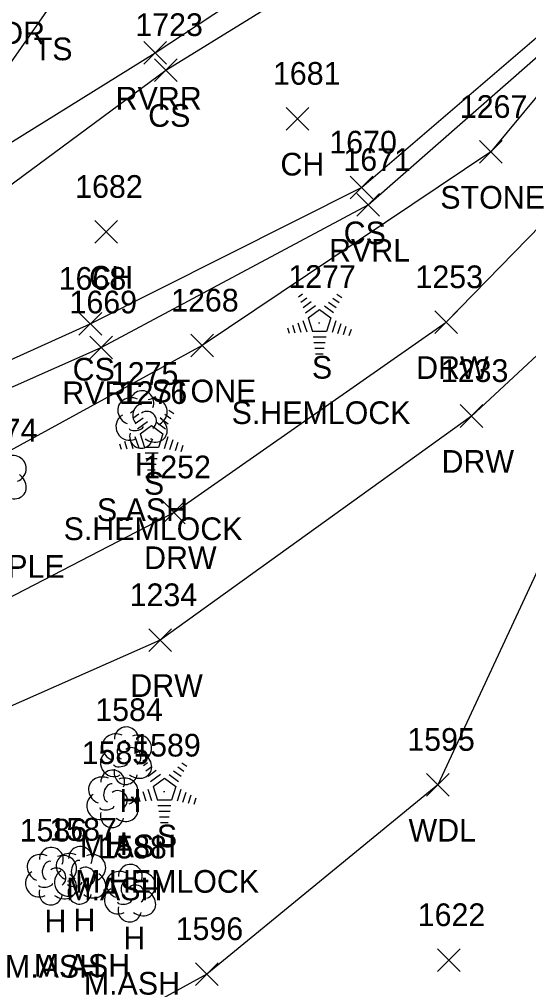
# Model space of a CAD drawing. Extents: x 1621633 to 1624015, y 417863 to 420979.
# Drawn here: x 1621938.6 to 1621983.5, y 417982.6 to 418067.9 of the extents above; entities that cross this region are included whole.
import ezdxf

# ---------------------------------------------------------------- set-up
doc = ezdxf.new("R2010")
doc.units = 0
for name, color, linetype in [('L_A', 7, 'Continuous'), ('L_C', 7, 'Continuous'), ('L_I', 7, 'Continuous'), ('L_TIC', 7, 'Continuous'), ('LASF', 7, 'Continuous'), ('LAWA', 7, 'Continuous'), ('LAWE', 7, 'Continuous'), ('LELB', 7, 'Continuous'), ('LTC', 7, 'Continuous'), ('LTD', 7, 'Continuous'), ('R_A', 7, 'Continuous'), ('R_I', 7, 'Continuous'), ('R_TIC', 7, 'Continuous'), ('RDW', 7, 'Continuous')]:
    doc.layers.add(name, color=color, linetype=linetype)

msp = doc.modelspace()

# ---------------------------------------------------------------- linework, layer by layer
at = {"layer": 'L_TIC'}
for points in [[(1621949.617, 418063.927), (1621951.617, 418065.927)], [(1621951.617, 418063.927), (1621949.617, 418065.927)], [(1621950.553, 418062.416), (1621952.553, 418064.416)], [(1621952.553, 418062.416), (1621950.553, 418064.416)], [(1621962.154, 418058.125), (1621964.154, 418060.125)], [(1621964.154, 418058.125), (1621962.154, 418060.125)], [(1621979.179, 418055.204), (1621981.179, 418057.204)], [(1621981.179, 418055.204), (1621979.179, 418057.204)], [(1621967.773, 418052.066), (1621969.773, 418054.066)], [(1621969.773, 418052.066), (1621967.773, 418054.066)], [(1621968.359, 418050.535), (1621970.359, 418052.535)], [(1621970.359, 418050.535), (1621968.359, 418052.535)], [(1621945.302, 418048.158), (1621947.302, 418050.158)], [(1621947.302, 418048.158), (1621945.302, 418050.158)], [(1621943.897, 418040.057), (1621945.897, 418042.057)], [(1621945.897, 418040.057), (1621943.897, 418042.057)], [(1621944.859, 418037.978), (1621946.859, 418039.978)], [(1621946.859, 418037.978), (1621944.859, 418039.978)], [(1621953.756, 418038.139), (1621955.756, 418040.139)], [(1621955.756, 418038.139), (1621953.756, 418040.139)], [(1621974.506, 417999.432), (1621976.506, 418001.432)], [(1621976.506, 417999.432), (1621974.506, 418001.432)], [(1621975.473, 417983.985), (1621977.473, 417985.985)], [(1621977.473, 417983.985), (1621975.473, 417985.985)], [(1621954.157, 417982.756), (1621956.157, 417984.756)], [(1621956.157, 417982.756), (1621954.157, 417984.756)]]:
    msp.add_lwpolyline(points, dxfattribs=at)
at = {"layer": 'LASF'}
msp.add_lwpolyline([(1622002.675, 418093.219), (1621997.296, 418076.86), (1621980.179, 418056.204), (1621954.756, 418039.139), (1621928.826, 418024.949), (1621900.016, 418015.523), (1621882.357, 418011.741)], dxfattribs=at)
at = {"layer": 'LAWA'}
msp.add_lwpolyline([(1622001.004, 418030.107), (1621986.32, 418023.658), (1621975.506, 418000.432), (1621955.157, 417983.756), (1621932.198, 417971.155), (1621904.748, 417967.466), (1621879.49, 417952.716), (1621860.189, 417941.587), (1621844.309, 417921.469), (1621821.118, 417913.626), (1621798.12, 417906.333), (1621768.531, 417901.526), (1621742.571, 417889.758), (1621727.863, 417881.174)], dxfattribs=at)
at = {"layer": 'LAWE'}
for points in [[(1621694.469, 417944.857), (1621713.846, 417956.733), (1621742.172, 417966.049), (1621760.532, 417975.456), (1621777.237, 417983.398), (1621792.696, 417991.301), (1621817.095, 418001.163), (1621844.467, 418008.037), (1621871.363, 418013.308), (1621897.422, 418019.495), (1621922.912, 418028.804), (1621945.859, 418038.978), (1621969.359, 418051.535), (1621990.012, 418069.674), (1621996.064, 418084.217), (1621996.533, 418092.287)], [(1621682.822, 417967.998), (1621698.064, 417979.126), (1621716.448, 417990.621), (1621740.687, 418004.296), (1621760.276, 418012.676), (1621779.786, 418018.1), (1621807.782, 418023.044), (1621832.841, 418028.899), (1621852.452, 418034.783), (1621876.37, 418040.125), (1621904.646, 418043.594), (1621931.259, 418052.925), (1621950.617, 418064.927), (1621964.804, 418074.349), (1621971.864, 418081.724)]]:
    msp.add_lwpolyline(points, dxfattribs=at)
at = {"layer": 'LELB'}
for points in [[(1621694.018, 417945.604), (1621713.058, 417958.392), (1621741.418, 417968.002), (1621759.92, 417977.729), (1621776.332, 417984.988), (1621792.046, 417992.579), (1621816.284, 418002.68), (1621844.088, 418009.589), (1621869.849, 418015.692), (1621896.837, 418021.913), (1621921.805, 418030.632), (1621944.897, 418041.057), (1621968.773, 418053.066), (1621989.111, 418070.538), (1621994.262, 418084.512), (1621994.522, 418092.07)], [(1621714.218, 417979.319), (1621742.211, 418002.577), (1621762.579, 418009.214), (1621780.28, 418013.608), (1621808.258, 418019.376), (1621833.473, 418026.83), (1621853.516, 418030.646), (1621878.098, 418035.973), (1621904.446, 418042.094), (1621933.372, 418049.997), (1621951.553, 418063.416), (1621967.003, 418072.955), (1621972.682, 418081.713), (1621977.304, 418089.793)], [(1621962.893, 418084.645), (1621941.499, 418069.284), (1621934.526, 418059.292), (1621911.153, 418049.766), (1621884.836, 418045.66), (1621868.891, 418041.418), (1621850.259, 418038.198), (1621830.712, 418031.899), (1621803.346, 418026.98), (1621784.312, 418024.309)]]:
    msp.add_lwpolyline(points, dxfattribs=at)
at = {"layer": 'LTC'}
for p, q in [((1621963.223, 418043.433), (1621963.578, 418043.691)), ((1621963.433, 418042.968), (1621963.962, 418043.352)), ((1621966.25, 418043.325), (1621966.8, 418042.926)), ((1621966.621, 418043.674), (1621967.041, 418043.369)), ((1621963.642, 418042.502), (1621964.346, 418043.013)), ((1621963.852, 418042.036), (1621964.73, 418042.674)), ((1621965.508, 418042.629), (1621966.318, 418042.04)), ((1621965.879, 418042.977), (1621966.558, 418042.483)), ((1621964.076, 418041.581), (1621965.088, 418042.316)), ((1621964.076, 418041.581), (1621964.463, 418040.388)), ((1621965.088, 418042.316), (1621966.085, 418041.591)), ((1621966.085, 418041.591), (1621965.694, 418040.388)), ((1621962.256, 418040.712), (1621962.408, 418040.244)), ((1621962.711, 418040.929), (1621962.923, 418040.277)), ((1621963.166, 418041.146), (1621963.438, 418040.31)), ((1621963.622, 418041.362), (1621963.953, 418040.343)), ((1621966.523, 418041.32), (1621966.185, 418040.28)), ((1621966.967, 418041.069), (1621966.68, 418040.185)), ((1621967.412, 418040.819), (1621967.175, 418040.09)), ((1621965.694, 418040.388), (1621964.463, 418040.388)), ((1621965.656, 418039.888), (1621964.511, 418039.888)), ((1621967.856, 418040.569), (1621967.669, 418039.995)), ((1621965.572, 418039.388), (1621964.583, 418039.388)), ((1621965.488, 418038.888), (1621964.656, 418038.888)), ((1621965.404, 418038.388), (1621964.729, 418038.388)), ((1621948.426, 418033.206), (1621948.78, 418033.463)), ((1621948.635, 418032.74), (1621949.164, 418033.124)), ((1621951.453, 418033.098), (1621952.002, 418032.699)), ((1621951.824, 418033.446), (1621952.243, 418033.142)), ((1621948.845, 418032.274), (1621949.549, 418032.786)), ((1621949.054, 418031.809), (1621949.933, 418032.447)), ((1621950.711, 418032.401), (1621951.52, 418031.812)), ((1621951.082, 418032.749), (1621951.761, 418032.256)), ((1621949.279, 418031.354), (1621950.291, 418032.088)), ((1621949.279, 418031.354), (1621949.666, 418030.16)), ((1621950.291, 418032.088), (1621951.288, 418031.363)), ((1621951.288, 418031.363), (1621950.897, 418030.16)), ((1621947.458, 418030.485), (1621947.61, 418030.017)), ((1621947.914, 418030.702), (1621948.125, 418030.05)), ((1621948.369, 418030.918), (1621948.64, 418030.083)), ((1621948.824, 418031.134), (1621949.155, 418030.115)), ((1621951.725, 418031.092), (1621951.387, 418030.053)), ((1621952.17, 418030.842), (1621951.882, 418029.957)), ((1621952.614, 418030.592), (1621952.377, 418029.862)), ((1621950.897, 418030.16), (1621949.666, 418030.16)), ((1621950.858, 418029.66), (1621949.714, 418029.66)), ((1621953.059, 418030.342), (1621952.872, 418029.767)), ((1621950.774, 418029.16), (1621949.786, 418029.16)), ((1621950.691, 418028.66), (1621949.859, 418028.66)), ((1621950.607, 418028.16), (1621949.932, 418028.16)), ((1621949.569, 418002.134), (1621949.924, 418002.391)), ((1621952.967, 418002.374), (1621953.387, 418002.069)), ((1621949.779, 418001.668), (1621950.308, 418002.052)), ((1621949.988, 418001.202), (1621950.692, 418001.714)), ((1621952.225, 418001.677), (1621952.905, 418001.184)), ((1621952.596, 418002.026), (1621953.146, 418001.626)), ((1621950.198, 418000.736), (1621951.076, 418001.374)), ((1621950.422, 418000.281), (1621951.434, 418001.016)), ((1621951.434, 418001.016), (1621952.431, 418000.291)), ((1621951.854, 418001.329), (1621952.664, 418000.74)), ((1621949.512, 417999.846), (1621949.784, 417999.011)), ((1621949.968, 418000.062), (1621950.299, 417999.043)), ((1621950.422, 418000.281), (1621950.81, 417999.088)), ((1621952.431, 418000.291), (1621952.04, 417999.088)), ((1621952.869, 418000.02), (1621952.531, 417998.981)), ((1621953.313, 417999.77), (1621953.026, 417998.885)), ((1621948.602, 417999.413), (1621948.754, 417998.945)), ((1621949.057, 417999.629), (1621949.269, 417998.978)), ((1621952.04, 417999.088), (1621950.81, 417999.088)), ((1621953.758, 417999.52), (1621953.521, 417998.79)), ((1621954.202, 417999.269), (1621954.015, 417998.695)), ((1621952.002, 417998.588), (1621950.857, 417998.588)), ((1621951.918, 417998.088), (1621950.93, 417998.088)), ((1621951.834, 417997.588), (1621951.002, 417997.588)), ((1621951.75, 417997.088), (1621951.075, 417997.088))]:
    msp.add_line(p, q, dxfattribs=at)
at = {"layer": 'LTD'}
for p, q in [((1621949.394, 418032.678), (1621949.394, 418032.678)), ((1621949.394, 418032.678), (1621949.394, 418032.678)), ((1621948.027, 418003.051), (1621948.027, 418003.051)), ((1621948.027, 418003.051), (1621948.027, 418003.051)), ((1621946.826, 417999.257), (1621946.826, 417999.257)), ((1621946.826, 417999.257), (1621946.826, 417999.257)), ((1621941.421, 417992.436), (1621941.421, 417992.436)), ((1621941.421, 417992.436), (1621941.421, 417992.436)), ((1621943.981, 417992.514), (1621943.981, 417992.514)), ((1621943.981, 417992.514), (1621943.981, 417992.514)), ((1621948.375, 417990.942), (1621948.375, 417990.942)), ((1621948.375, 417990.942), (1621948.375, 417990.942))]:
    msp.add_line(p, q, dxfattribs=at)
for centre in [(1621949.441, 418034.112), (1621948.074, 418004.485), (1621946.873, 418000.691), (1621941.468, 417993.87), (1621944.027, 417993.948), (1621948.421, 417992.376)]:
    msp.add_arc(centre, 1.047, 335.52715, 180.95627, dxfattribs=at)
for centre, major_axis, ratio, start_param, end_param in [((1621948.602, 418033.345), (1.21, -0.512), 0.895232, 1.570796, 4.712389), ((1621949.186, 418033.136), (-0.208, -0.792), 0.645439, 3.141593, 6.283185), ((1621950.436, 418033.262), (-1.141, -0.483), 0.949671, 1.570796, 4.712389), ((1621948.311, 418031.97), (0.584, -1.042), 0.959034, 3.141593, 6.283185), ((1621949.894, 418032.511), (-0.5, 0.667), 0.989748, 3.141593, 6.283185), ((1621950.394, 418031.845), (-1.09, 0.792), 0.841452, 1.570796, 4.712389), ((1621949.394, 418031.178), (0.265, 1.061), 0.942809, 1.570796, 4.712389), ((1621948.936, 418031.928), (-0.625, -0.083), 0.423636, 0, 3.141593), ((1621938.022, 418028.269), (-1.141, -0.483), 0.949671, 1.570796, 4.712389), ((1621937.98, 418026.852), (-1.09, 0.792), 0.841452, 1.570796, 4.712389), ((1621947.235, 418003.718), (1.21, -0.512), 0.895232, 1.570796, 4.712389), ((1621949.068, 418003.635), (-1.141, -0.483), 0.949671, 1.570796, 4.712389), ((1621947.818, 418003.51), (-0.208, -0.792), 0.645439, 3.141593, 6.283185), ((1621946.944, 418002.343), (0.584, -1.042), 0.959034, 3.141593, 6.283185), ((1621948.527, 418002.885), (-0.5, 0.667), 0.989748, 3.141593, 6.283185), ((1621949.027, 418002.218), (-1.09, 0.792), 0.841452, 1.570796, 4.712389), ((1621947.569, 418002.301), (-0.625, -0.083), 0.423636, 0, 3.141593), ((1621948.027, 418001.551), (0.265, 1.061), 0.942809, 1.570796, 4.712389), ((1621946.034, 417999.923), (1.21, -0.512), 0.895232, 1.570796, 4.712389), ((1621946.617, 417999.715), (-0.208, -0.792), 0.645439, 3.141593, 6.283185), ((1621947.867, 417999.84), (-1.141, -0.483), 0.949671, 1.570796, 4.712389), ((1621947.326, 417999.09), (-0.5, 0.667), 0.989748, 3.141593, 6.283185), ((1621945.743, 417998.548), (0.584, -1.042), 0.959034, 3.141593, 6.283185), ((1621947.826, 417998.424), (-1.09, 0.792), 0.841452, 1.570796, 4.712389), ((1621946.826, 417997.757), (0.265, 1.061), 0.942809, 1.570796, 4.712389), ((1621946.368, 417998.507), (-0.625, -0.083), 0.423636, 0, 3.141593), ((1621940.629, 417993.103), (1.21, -0.512), 0.895232, 1.570796, 4.712389), ((1621941.212, 417992.895), (-0.208, -0.792), 0.645439, 3.141593, 6.283185), ((1621943.189, 417993.18), (1.21, -0.512), 0.895232, 1.570796, 4.712389), ((1621942.462, 417993.02), (-1.141, -0.483), 0.949671, 1.570796, 4.712389), ((1621943.772, 417992.972), (-0.208, -0.792), 0.645439, 3.141593, 6.283185), ((1621945.022, 417993.097), (-1.141, -0.483), 0.949671, 1.570796, 4.712389), ((1621941.921, 417992.27), (-0.5, 0.667), 0.989748, 3.141593, 6.283185), ((1621944.481, 417992.347), (-0.5, 0.667), 0.989748, 3.141593, 6.283185), ((1621947.583, 417991.609), (1.21, -0.512), 0.895232, 1.570796, 4.712389), ((1621940.338, 417991.728), (0.584, -1.042), 0.959034, 3.141593, 6.283185), ((1621942.897, 417991.805), (0.584, -1.042), 0.959034, 3.141593, 6.283185), ((1621942.421, 417991.603), (-1.09, 0.792), 0.841452, 1.570796, 4.712389), ((1621944.981, 417991.68), (-1.09, 0.792), 0.841452, 1.570796, 4.712389), ((1621948.166, 417991.401), (-0.208, -0.792), 0.645439, 3.141593, 6.283185), ((1621949.416, 417991.526), (-1.141, -0.483), 0.949671, 1.570796, 4.712389), ((1621941.421, 417990.936), (0.265, 1.061), 0.942809, 1.570796, 4.712389), ((1621940.963, 417991.686), (-0.625, -0.083), 0.423636, 0, 3.141593), ((1621943.981, 417991.014), (0.265, 1.061), 0.942809, 1.570796, 4.712389), ((1621943.522, 417991.764), (-0.625, -0.083), 0.423636, 0, 3.141593), ((1621947.291, 417990.234), (0.584, -1.042), 0.959034, 3.141593, 6.283185), ((1621948.875, 417990.776), (-0.5, 0.667), 0.989748, 3.141593, 6.283185), ((1621949.375, 417990.109), (-1.09, 0.792), 0.841452, 1.570796, 4.712389), ((1621948.375, 417989.442), (0.265, 1.061), 0.942809, 1.570796, 4.712389), ((1621947.916, 417990.192), (-0.625, -0.083), 0.423636, 0, 3.141593)]:
    msp.add_ellipse(centre, major_axis=major_axis, ratio=ratio, start_param=start_param, end_param=end_param, dxfattribs=at)
at = {"layer": 'R_TIC'}
for points in [[(1621975.225, 418040.199), (1621977.225, 418042.199)], [(1621977.225, 418040.199), (1621975.225, 418042.199)], [(1621977.461, 418031.933), (1621979.461, 418033.933)], [(1621979.461, 418031.933), (1621977.461, 418033.933)], [(1621951.262, 418023.445), (1621953.262, 418025.445)], [(1621953.262, 418023.445), (1621951.262, 418025.445)], [(1621950.05, 418012.179), (1621952.05, 418014.179)], [(1621952.05, 418012.179), (1621950.05, 418014.179)]]:
    msp.add_lwpolyline(points, dxfattribs=at)
at = {"layer": 'RDW'}
for points in [[(1622068.286, 418109.151), (1622048.314, 418092.064), (1622031.513, 418075.622), (1622017.283, 418070.416), (1621999.079, 418052.056), (1621978.461, 418032.933), (1621951.05, 418013.179), (1621921.756, 418000.239), (1621894.363, 417990.232), (1621865.95, 417979.751)], [(1621869.66, 417990.005), (1621898.189, 417999.842), (1621925.17, 418010.412), (1621952.262, 418024.445), (1621976.225, 418041.199), (1621996.59, 418062.054), (1622014.164, 418083.988), (1622019.779, 418092.569), (1622014.506, 418097.249)]]:
    msp.add_lwpolyline(points, dxfattribs=at)

# ---------------------------------------------------------------- texts
at = {"layer": 'L_A'}
for s, p in [('WDR', (1621934.515, 418065.696)), ('TS', (1621939.909, 418064.284)), ('RVRR', (1621947.128, 418059.927)), ('CS', (1621949.994, 418058.416)), ('CH', (1621961.642, 418054.125)), ('STONE', (1621975.723, 418051.204)), ('CS', (1621967.214, 418048.066)), ('RVRL', (1621965.926, 418046.535)), ('CH', (1621944.791, 418044.158)), ('CS', (1621943.338, 418036.057)), ('S', (1621964.414, 418036.225)), ('RVRL', (1621942.426, 418033.978)), ('STONE', (1621950.299, 418034.139)), ('H', (1621948.827, 418027.678)), ('S', (1621949.616, 418025.998)), ('H', (1621947.46, 417998.051)), ('WDL', (1621972.923, 417995.432)), ('S', (1621950.76, 417994.925)), ('H', (1621946.259, 417994.257)), ('H', (1621943.414, 417987.514)), ('H', (1621940.854, 417987.436)), ('H', (1621947.808, 417985.942))]:
    msp.add_text(s, height=2, dxfattribs=at).set_placement(p)
at = {"layer": 'L_C'}
for s, p in [('S.HEMLOCK', (1621957.343, 418032.225)), ('S.ASH', (1621945.473, 418023.678)), ('S.HEMLOCK', (1621942.545, 418021.998)), ('S.MAPLE', (1621931.043, 418018.686)), ('M.ASH', (1621943.98, 417994.051)), ('M.HEMLOCK', (1621943.563, 417990.925)), ('M.ASH', (1621942.779, 417990.257)), ('M.ASH', (1621937.374, 417983.436)), ('M.ASH', (1621939.933, 417983.514)), ('M.ASH', (1621944.327, 417981.942))]:
    msp.add_text(s, height=2, dxfattribs=at).set_placement(p)
at = {"layer": 'L_I'}
for s, p in [('1723', (1621948.861, 418066.416)), ('1681', (1621960.981, 418062.125)), ('1267', (1621977.439, 418059.204)), ('1670', (1621965.946, 418056.066)), ('1671', (1621967.186, 418054.535)), ('1682', (1621943.562, 418052.158)), ('1668', (1621942.109, 418044.057)), ('1277', (1621962.335, 418044.225)), ('1268', (1621952.016, 418042.139)), ('1669', (1621943.064, 418041.978)), ('1275', (1621946.701, 418035.678)), ('1276', (1621947.482, 418033.998)), ('1274', (1621934.287, 418030.686)), ('1584', (1621945.334, 418006.051)), ('1589', (1621948.673, 418002.925)), ('1595', (1621972.813, 418003.432)), ('1585', (1621944.133, 418002.257)), ('1586', (1621938.673, 417995.436)), ('1587', (1621941.288, 417995.514)), ('1588', (1621945.682, 417993.942)), ('1622', (1621973.733, 417987.985)), ('1596', (1621952.409, 417986.756))]:
    msp.add_text(s, height=2, dxfattribs=at).set_placement(p)
at = {"layer": 'LTC'}
for p in [(1621964.971, 418041.329), (1621950.173, 418031.102), (1621951.317, 418000.029)]:
    msp.add_text('.', height=1.037, rotation=270, dxfattribs=at).set_placement(p)
at = {"layer": 'R_A'}
for p in [(1621973.595, 418036.199), (1621975.831, 418027.933), (1621949.632, 418019.445), (1621948.42, 418008.179)]:
    msp.add_text('DRW', height=2, dxfattribs=at).set_placement(p)
at = {"layer": 'R_I'}
for s, p in [('1253', (1621973.532, 418044.199)), ('1233', (1621975.768, 418035.933)), ('1252', (1621949.569, 418027.445)), ('1234', (1621948.357, 418016.179))]:
    msp.add_text(s, height=2, dxfattribs=at).set_placement(p)

doc.saveas('drawing.dxf')
